Omron CX-Programmer project NuevoProyecto (CX-Programmer 9.50)

# PLC NewPLC1: CP1L-E EM

## Program P7_2 (cyclic task 0)
Local symbols
AUX 15.00 BOOL
Ab 100.01 BOOL
As 100.00 BOOL
B 100.02 BOOL
C 100.03 BOOL
Etapa_0 10.00 BOOL
Etapa_1 10.01 BOOL
Etapa_2 10.02 BOOL
Etapa_3 10.03 BOOL
Etapa_4 10.04 BOOL
Etapa_5 10.05 BOOL
Etapa_6 10.06 BOOL
Etapa_7 10.07 BOOL
a_0 0.01 BOOL
a_1 0.02 BOOL
a_2 0.03 BOOL
b_0 0.04 BOOL
b_1 0.05 BOOL
c_0 0.06 BOOL
c_1 0.07 BOOL
m 0.00 BOOL

### Section Sección1_Programa_principal
; Programa principal (Etapas 0 ... 7)

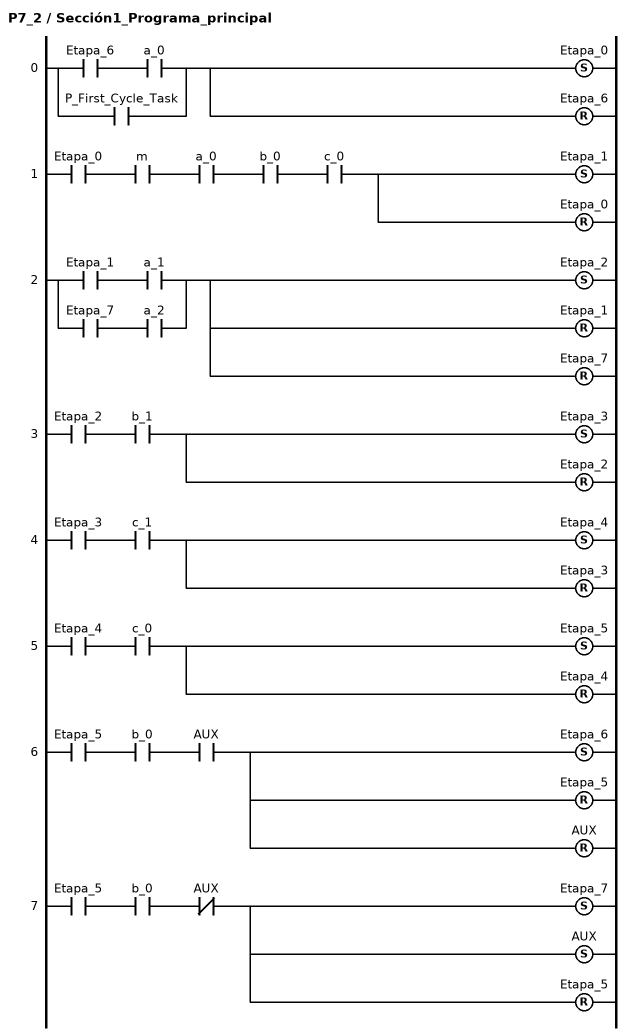
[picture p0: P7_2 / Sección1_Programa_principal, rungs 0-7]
; rung 0
LD Etapa_6
AND a_0
OR P_First_Cycle_Task
SET Etapa_0
RSET Etapa_6
; rung 1
LD Etapa_0
AND m
AND a_0
AND b_0
AND c_0
SET Etapa_1
RSET Etapa_0
; rung 2
LD Etapa_1
AND a_1
LD Etapa_7
AND a_2
ORLD
SET Etapa_2
RSET Etapa_1
RSET Etapa_7
; rung 3
LD Etapa_2
AND b_1
SET Etapa_3
RSET Etapa_2
; rung 4
LD Etapa_3
AND c_1
SET Etapa_4
RSET Etapa_3
; rung 5
LD Etapa_4
AND c_0
SET Etapa_5
RSET Etapa_4
; rung 6
LD Etapa_5
AND b_0
AND AUX
SET Etapa_6
RSET Etapa_5
RSET AUX
; rung 7
LD Etapa_5
AND b_0
ANDNOT AUX
SET Etapa_7
SET AUX
RSET Etapa_5

### Section Sección2_Salidas

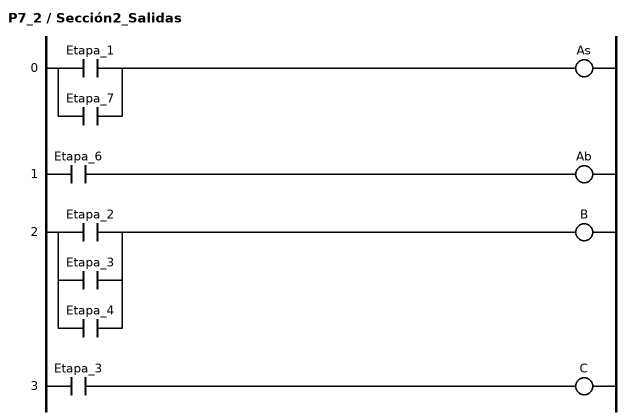
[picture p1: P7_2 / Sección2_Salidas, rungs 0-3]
; rung 0
LD Etapa_1
OR Etapa_7
OUT As
; rung 1
LD Etapa_6
OUT Ab
; rung 2
LD Etapa_2
OR Etapa_3
OR Etapa_4
OUT B
; rung 3
LD Etapa_3
OUT C

### Section Sección3_END
; rung 0: Fin de programa
END(001)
